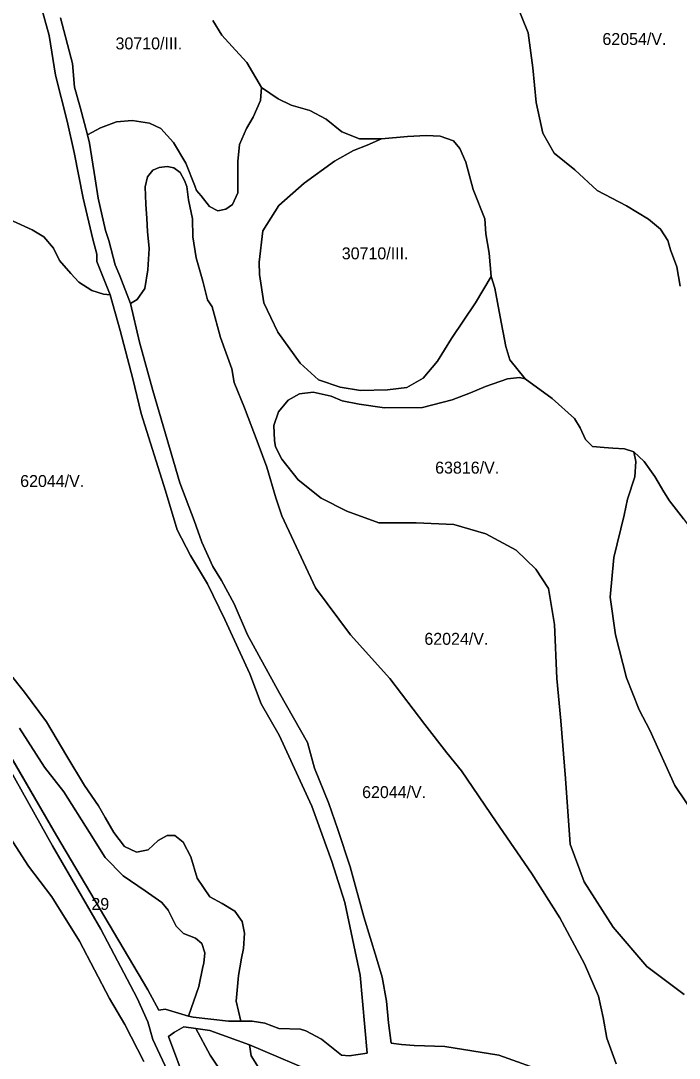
# Model space of a CAD drawing. Extents: x -521621 to -516761, y -1190184 to -1184927.
# Drawn here: x -519249 to -518423, y -1189393 to -1188092 of the extents above; entities that cross this region are included whole.
import ezdxf

# ---------------------------------------------------------------- set-up
doc = ezdxf.new("R2010")
doc.units = 0
doc.layers.add('BPEJ_s', color=7, linetype='Continuous')

msp = doc.modelspace()

# ---------------------------------------------------------------- linework, layer by layer
at = {"layer": 'BPEJ_s'}
for p, q in [((-519204.4, -1189113.9), (-519310.7, -1188931.3)), ((-519250.7, -1188979.3), (-519219.5, -1189028.1)), ((-519219.5, -1189028.1), (-519195.4, -1189059.3)), ((-519195.4, -1189059.3), (-519163.2, -1189110)), ((-519163.2, -1189110), (-519143.6, -1189141.7)), ((-519090, -1189307.3), (-519204.4, -1189113.9)), ((-519143.6, -1189141.7), (-519121, -1189164.3)), ((-519121, -1189164.3), (-519093.4, -1189183.5)), ((-519093.4, -1189183.5), (-519072.3, -1189198)), ((-519072.3, -1189198), (-519064.2, -1189207.6)), ((-519064.2, -1189207.6), (-519054.2, -1189227.7)), ((-519054.2, -1189227.7), (-519045.1, -1189236.8)), ((-519045.1, -1189236.8), (-519030, -1189242.8)), ((-519030, -1189242.8), (-519022, -1189249.3)), ((-519022, -1189249.3), (-519018.5, -1189260.9)), ((-519018.5, -1189260.9), (-519019.5, -1189274)), ((-519021.1, -1189278.8), (-519025.8, -1189303.4)), ((-519019.5, -1189274), (-519021.1, -1189278.8)), ((-519076.3, -1189332.8), (-519090, -1189307.3)), ((-519025.8, -1189303.4), (-519038.7, -1189340.3)), ((-519068.1, -1189331.9), (-519076.3, -1189332.8)), ((-519038.7, -1189340.3), (-519068.1, -1189331.9))]:
    msp.add_line(p, q, dxfattribs=at)
for points in [[(-519310.7, -1188931.3), (-519204.4, -1189113.9), (-519090, -1189307.3), (-519076.3, -1189332.8), (-519068.1, -1189331.9), (-519038.7, -1189340.3), (-519033.1, -1189341.9), (-518988.7, -1189346.7), (-518973.2, -1189346.8), (-518959.1, -1189346.8), (-518943, -1189349.4), (-518925.4, -1189356), (-518898.4, -1189356.8), (-518891.6, -1189358.8), (-518872.1, -1189369.4), (-518846.8, -1189389.4), (-518837.5, -1189390.4), (-518814.6, -1189387), (-518823.5, -1189289), (-518842.7, -1189197.8), (-518859.1, -1189146.7), (-518884.3, -1189077.1), (-518925.3, -1188988), (-518947.6, -1188949), (-518962.1, -1188911.3), (-518993.3, -1188842.9), (-519014.9, -1188798.4), (-519036.3, -1188762.9), (-519053.3, -1188730.6), (-519067.7, -1188681.6), (-519098.2, -1188584.8), (-519108.8, -1188541.2), (-519124.4, -1188480.7), (-519137.3, -1188435.8), (-519153.9, -1188394.1), (-519153.7, -1188385.1), (-519159, -1188366.1), (-519170.9, -1188314.7), (-519182.1, -1188257.4), (-519191.2, -1188218), (-519205.6, -1188160.4), (-519213.8, -1188110.8), (-519224.7, -1188071.4)], [(-519224.7, -1188071.4), (-519213.8, -1188110.8), (-519205.6, -1188160.4), (-519191.2, -1188218), (-519182.1, -1188257.4), (-519170.9, -1188314.7), (-519159, -1188366.1), (-519153.7, -1188385.1), (-519153.9, -1188394.1), (-519137.3, -1188435.8), (-519145.7, -1188435.1), (-519160.1, -1188430.5), (-519176.6, -1188419.9), (-519186.3, -1188409.1), (-519200.9, -1188393), (-519208.2, -1188377.4), (-519220.5, -1188363), (-519234.9, -1188354.2), (-519258.9, -1188343.4)], [(-518422.2, -1188425.1), (-518426.5, -1188400.9), (-518434.5, -1188379.5), (-518437.8, -1188367.6), (-518447, -1188353.4), (-518462, -1188340.9), (-518489.5, -1188324.2), (-518526.2, -1188305), (-518554.5, -1188279.1), (-518580.4, -1188258.3), (-518594.6, -1188233.2), (-518602.9, -1188194.8), (-518607.1, -1188151.4), (-518612.9, -1188107.2), (-518629.6, -1188065.5)], [(-518629.6, -1188065.5), (-518612.9, -1188107.2), (-518607.1, -1188151.4), (-518602.9, -1188194.8), (-518594.6, -1188233.2), (-518580.4, -1188258.3), (-518554.5, -1188279.1), (-518526.2, -1188305), (-518489.5, -1188324.2), (-518462, -1188340.9), (-518447, -1188353.4), (-518437.8, -1188367.6), (-518434.5, -1188379.5), (-518426.5, -1188400.9), (-518422.2, -1188425.1)], [(-519008.5, -1188091.9), (-518997.1, -1188110.1), (-518980, -1188129.2), (-518965.7, -1188144.7), (-518947.5, -1188176), (-518948.7, -1188192.3), (-518957.8, -1188213.3), (-518966.1, -1188227.2), (-518974.8, -1188247.4), (-518977.2, -1188268.8), (-518977.2, -1188308.1), (-518983.6, -1188322.8), (-518991.9, -1188328.3), (-519002.2, -1188330.7), (-519012.5, -1188325.2), (-519023.2, -1188311.7), (-519028.8, -1188304.9), (-519031.1, -1188299.4), (-519042.1, -1188270.6), (-519057.6, -1188244.7), (-519073.4, -1188227.2), (-519087.6, -1188220.5), (-519109.5, -1188217.4), (-519129.3, -1188219.1), (-519149.3, -1188226.4), (-519165.7, -1188235.3), (-519174.9, -1188200.4), (-519181.7, -1188175.6), (-519184.3, -1188145.8), (-519199.5, -1188088.7)], [(-519199.5, -1188088.7), (-519184.3, -1188145.8), (-519181.7, -1188175.6), (-519174.9, -1188200.4), (-519165.7, -1188235.3), (-519163, -1188245.8), (-519155.8, -1188290.4), (-519152, -1188314.5), (-519142.9, -1188355.4), (-519138.9, -1188367.7), (-519130.8, -1188398.4), (-519124.9, -1188412), (-519111.8, -1188446.6), (-519100.2, -1188495.2), (-519083.8, -1188556), (-519049.7, -1188671.8), (-519031.7, -1188719.1), (-519022.3, -1188746.2), (-519008.4, -1188776.5), (-518997.4, -1188794.1), (-518981.8, -1188823.6), (-518964.8, -1188862.2), (-518924.6, -1188935.3), (-518889.5, -1188997.5), (-518880.9, -1189029.4), (-518863, -1189074), (-518851.7, -1189106.3), (-518836.2, -1189153.4), (-518818.8, -1189215.9), (-518803.2, -1189267.6), (-518795.9, -1189291.4), (-518790.7, -1189321.8), (-518788, -1189348.8), (-518784.8, -1189374.2), (-518771.9, -1189376), (-518756, -1189377.2), (-518717.4, -1189378.6), (-518649.6, -1189389.2), (-518586.3, -1189412)], [(-518417.8, -1188716.8), (-518435.5, -1188694.4), (-518442.8, -1188683), (-518453.9, -1188663.6), (-518467.4, -1188644.9), (-518480.4, -1188633), (-518491.9, -1188629.1), (-518506.6, -1188628.3), (-518517.7, -1188627.5), (-518532, -1188625.9), (-518541.1, -1188617.2), (-518547.8, -1188602.9), (-518554.6, -1188591.1), (-518582.8, -1188566), (-518616.7, -1188541.3), (-518635.7, -1188517.6), (-518641, -1188500.9), (-518647.8, -1188463.6), (-518654.5, -1188427.5), (-518659.2, -1188412.8), (-518661.6, -1188383.5), (-518666, -1188359.3), (-518667.2, -1188340.6), (-518681.9, -1188303.7), (-518691, -1188269.6), (-518698.5, -1188252.6), (-518706.4, -1188242.6), (-518723.1, -1188237.1), (-518740.9, -1188235.9), (-518764.3, -1188237.5), (-518796.8, -1188240.3), (-518824.2, -1188240.3), (-518846.4, -1188231.5), (-518866.2, -1188215.7), (-518886.8, -1188204.6), (-518910.2, -1188198.2), (-518926.5, -1188190.3), (-518947.5, -1188176), (-518965.7, -1188144.7), (-518980, -1188129.2), (-518997.1, -1188110.1), (-519008.5, -1188091.9)], [(-519165.7, -1188235.3), (-519149.3, -1188226.4), (-519129.3, -1188219.1), (-519109.5, -1188217.4), (-519087.6, -1188220.5), (-519073.4, -1188227.2), (-519057.6, -1188244.7), (-519042.1, -1188270.6), (-519031.1, -1188299.4), (-519028.8, -1188304.9), (-519023.2, -1188311.7), (-519012.5, -1188325.2), (-519002.2, -1188330.7), (-518991.9, -1188328.3), (-518983.6, -1188322.8), (-518977.2, -1188308.1), (-518977.2, -1188287.9), (-518977.2, -1188268.8), (-518974.8, -1188247.4), (-518966.1, -1188227.2), (-518957.8, -1188213.3), (-518948.7, -1188192.3), (-518947.5, -1188176)], [(-518947.5, -1188176), (-518926.5, -1188190.3), (-518910.2, -1188198.2), (-518886.8, -1188204.6), (-518866.2, -1188215.7), (-518846.4, -1188231.5), (-518824.2, -1188240.3), (-518796.8, -1188240.3)], [(-519111.8, -1188446.6), (-519124.9, -1188412), (-519130.8, -1188398.4), (-519138.9, -1188367.7), (-519142.9, -1188355.4), (-519152, -1188314.5), (-519155.8, -1188290.4), (-519163, -1188245.8), (-519165.7, -1188235.3)], [(-518796.8, -1188240.3), (-518814.7, -1188248.2), (-518832.1, -1188254.9), (-518855.9, -1188268.4), (-518893.6, -1188295.8), (-518925.7, -1188324), (-518945.5, -1188355.7), (-518950.3, -1188395), (-518949.9, -1188410.5), (-518944.3, -1188445.8), (-518926.9, -1188482.7), (-518898.7, -1188521.5), (-518875.7, -1188542.6), (-518848.8, -1188551.7), (-518823, -1188555.7), (-518789.3, -1188554.9), (-518765.1, -1188552.1), (-518744.5, -1188540.6), (-518726.7, -1188519.2), (-518709.2, -1188490.6), (-518679.1, -1188445.8), (-518659.2, -1188412.8)], [(-518586.3, -1189412), (-518649.6, -1189389.2), (-518717.4, -1189378.6), (-518756, -1189377.2), (-518771.9, -1189376), (-518784.8, -1189374.2), (-518788, -1189348.8), (-518790.7, -1189321.8), (-518795.9, -1189291.4), (-518803.2, -1189267.6), (-518818.8, -1189215.9), (-518836.2, -1189153.4), (-518851.7, -1189106.3), (-518863, -1189074), (-518880.9, -1189029.4), (-518889.5, -1188997.5), (-518924.6, -1188935.3), (-518964.8, -1188862.2), (-518981.8, -1188823.6), (-518997.4, -1188794.1), (-519008.4, -1188776.5), (-519022.3, -1188746.2), (-519031.7, -1188719.1), (-519049.7, -1188671.8), (-519083.8, -1188556), (-519100.2, -1188495.2), (-519111.8, -1188446.6), (-519103.4, -1188441.6), (-519093.8, -1188427.8), (-519089.9, -1188404.7), (-519088.4, -1188378), (-519090.5, -1188356.3), (-519091.1, -1188340.2), (-519092.2, -1188322.3), (-519093.4, -1188300.4), (-519090.5, -1188287.9), (-519083.6, -1188279.6), (-519075.5, -1188276.2), (-519065.5, -1188275), (-519057.2, -1188276.8), (-519049.2, -1188282.3), (-519044, -1188292.5), (-519041.1, -1188300), (-519039, -1188316.7), (-519033.8, -1188340.4), (-519033.4, -1188363.2), (-519029.4, -1188389.4), (-519020.7, -1188418.6), (-519015.1, -1188442), (-519009.4, -1188451), (-518998.8, -1188489.3), (-518984.6, -1188528.7), (-518981.5, -1188546), (-518968.6, -1188577.5), (-518951.5, -1188622.6), (-518940.5, -1188652.2), (-518929.4, -1188690.5), (-518921.7, -1188713.1), (-518879.6, -1188803.3), (-518835.5, -1188862.1), (-518786.5, -1188917.1), (-518742.4, -1188974.9), (-518714.9, -1189010.2), (-518696.5, -1189032.7), (-518653, -1189096.9), (-518608.5, -1189161.1), (-518573.3, -1189217), (-518542.3, -1189275), (-518524.7, -1189315.4), (-518518.7, -1189342), (-518514, -1189368), (-518502.4, -1189400.1)], [(-518502.4, -1189400.1), (-518514, -1189368), (-518518.7, -1189342), (-518524.7, -1189315.4), (-518542.3, -1189275), (-518573.3, -1189217), (-518608.5, -1189161.1), (-518653, -1189096.9), (-518696.5, -1189032.7), (-518714.9, -1189010.2), (-518742.4, -1188974.9), (-518786.5, -1188917.1), (-518835.5, -1188862.1), (-518879.6, -1188803.3), (-518921.7, -1188713.1), (-518929.4, -1188690.5), (-518940.5, -1188652.2), (-518951.5, -1188622.6), (-518968.6, -1188577.5), (-518981.5, -1188546), (-518984.6, -1188528.7), (-518998.8, -1188489.3), (-519009.4, -1188451), (-519015.1, -1188442), (-519020.7, -1188418.6), (-519029.4, -1188389.4), (-519033.4, -1188363.2), (-519033.8, -1188340.4), (-519039, -1188316.7), (-519041.1, -1188300), (-519044, -1188292.5), (-519049.2, -1188282.3), (-519057.2, -1188276.8), (-519065.5, -1188275), (-519075.5, -1188276.2), (-519083.6, -1188279.6), (-519090.5, -1188287.9), (-519093.4, -1188300.4), (-519092.2, -1188322.3), (-519091.1, -1188340.2), (-519090.5, -1188356.3), (-519088.4, -1188378), (-519089.9, -1188404.7), (-519093.8, -1188427.8), (-519103.4, -1188441.6), (-519111.8, -1188446.6)], [(-519258.9, -1188343.4), (-519234.9, -1188354.2), (-519220.5, -1188363), (-519208.2, -1188377.4), (-519200.9, -1188393), (-519186.3, -1188409.1), (-519176.6, -1188419.9), (-519160.1, -1188430.5), (-519145.7, -1188435.1), (-519137.3, -1188435.8), (-519124.4, -1188480.7), (-519108.8, -1188541.2), (-519098.2, -1188584.8), (-519067.7, -1188681.6), (-519053.3, -1188730.6), (-519036.3, -1188762.9), (-519014.9, -1188798.4), (-518993.3, -1188842.9), (-518962.1, -1188911.3), (-518947.6, -1188949), (-518925.3, -1188988), (-518884.3, -1189077.1), (-518859.1, -1189146.7), (-518842.7, -1189197.8), (-518823.5, -1189289), (-518814.6, -1189387), (-518837.5, -1189390.4), (-518846.8, -1189389.4), (-518872.1, -1189369.4), (-518891.6, -1189358.8), (-518898.4, -1189356.8), (-518925.4, -1189356), (-518943, -1189349.4), (-518959.1, -1189346.8), (-518973.2, -1189346.8), (-518978.9, -1189321.8), (-518976, -1189289.6), (-518974.6, -1189279.9), (-518972.3, -1189267.8), (-518969.7, -1189255.5), (-518968.8, -1189236.3), (-518971.7, -1189221.7), (-518980.9, -1189209), (-518996.7, -1189199.3), (-519012, -1189191), (-519028, -1189167.4), (-519036.1, -1189140.7), (-519045.6, -1189122.1), (-519056.2, -1189114.1), (-519065.7, -1189114.1), (-519076.8, -1189120.1), (-519089.3, -1189131.7), (-519103.9, -1189134.7), (-519119, -1189127.6), (-519132.6, -1189110), (-519143.6, -1189091.4), (-519151.7, -1189076.9), (-519169.2, -1189051.2), (-519191.4, -1189014.5), (-519217, -1188971.3), (-519244.6, -1188934), (-519284.3, -1188884.8)], [(-518659.2, -1188412.8), (-518654.5, -1188427.5), (-518647.8, -1188463.6), (-518641, -1188500.9), (-518635.7, -1188517.6), (-518616.7, -1188541.3)], [(-518417, -1189313.3), (-518464, -1189278), (-518506.2, -1189228.9), (-518542.4, -1189172), (-518560.1, -1189125), (-518566, -1189042.6), (-518571.8, -1188970), (-518576.7, -1188917.1), (-518579.7, -1188849.4), (-518587.5, -1188804.3), (-518603.2, -1188779.8), (-518627.7, -1188756.2), (-518665.9, -1188735.6), (-518706.1, -1188723.9), (-518753.2, -1188721.9), (-518800.2, -1188721.9), (-518840.4, -1188707.2), (-518872.5, -1188690.8), (-518901.5, -1188668), (-518921.9, -1188641.8), (-518929.6, -1188626.5), (-518931.1, -1188618.4), (-518931.9, -1188599.6), (-518925.9, -1188582.7), (-518914, -1188568.1), (-518899.8, -1188560.2), (-518882.5, -1188557.9), (-518859.8, -1188562.9), (-518846.3, -1188568.8), (-518824.8, -1188573.2), (-518792.9, -1188577.7), (-518745.2, -1188577.1), (-518708.3, -1188567.7), (-518685.2, -1188558.8), (-518666.2, -1188551), (-518638.9, -1188541.2), (-518623.7, -1188539.6), (-518616.7, -1188541.3), (-518582.8, -1188566), (-518554.6, -1188591.1), (-518547.8, -1188602.9), (-518541.1, -1188617.2), (-518532, -1188625.9), (-518517.7, -1188627.5), (-518506.6, -1188628.3), (-518491.9, -1188629.1), (-518480.4, -1188633), (-518477.7, -1188644.9), (-518479.2, -1188664), (-518488.4, -1188692.1), (-518492.5, -1188712.1), (-518505.2, -1188765.1), (-518510.1, -1188815.1), (-518503.2, -1188862.1), (-518489.5, -1188916.1), (-518473.8, -1188956.3), (-518460.1, -1188981.8), (-518428.8, -1189051.4), (-518400.3, -1189093.6)], [(-518616.7, -1188541.3), (-518623.7, -1188539.6), (-518638.9, -1188541.2), (-518666.2, -1188551), (-518685.2, -1188558.8), (-518708.3, -1188567.7), (-518745.2, -1188577.1), (-518792.9, -1188577.7), (-518824.8, -1188573.2), (-518846.3, -1188568.8), (-518859.8, -1188562.9), (-518882.5, -1188557.9), (-518899.8, -1188560.2), (-518914, -1188568.1), (-518925.9, -1188582.7), (-518931.9, -1188599.6), (-518931.1, -1188618.4), (-518929.6, -1188626.5), (-518921.9, -1188641.8), (-518901.5, -1188668), (-518872.5, -1188690.8), (-518840.4, -1188707.2), (-518800.2, -1188721.9), (-518753.2, -1188721.9), (-518706.1, -1188723.9), (-518665.9, -1188735.6), (-518627.7, -1188756.2), (-518603.2, -1188779.8), (-518587.5, -1188804.3), (-518579.7, -1188849.4), (-518576.7, -1188917.1), (-518571.8, -1188970), (-518566, -1189042.6), (-518560.1, -1189125), (-518542.4, -1189172), (-518506.2, -1189228.9), (-518464, -1189278), (-518417, -1189313.3)], [(-518400.3, -1189093.6), (-518428.8, -1189051.4), (-518460.1, -1188981.8), (-518473.8, -1188956.3), (-518489.5, -1188916.1), (-518503.2, -1188862.1), (-518510.1, -1188815.1), (-518505.2, -1188765.1), (-518492.5, -1188712.1), (-518488.4, -1188692.1), (-518479.2, -1188664), (-518477.7, -1188644.9), (-518480.4, -1188633)], [(-518480.4, -1188633), (-518467.4, -1188644.9), (-518453.9, -1188663.6), (-518442.8, -1188683), (-518435.5, -1188694.4), (-518417.8, -1188716.8), (-518378.9, -1188770)], [(-519284.3, -1188884.8), (-519244.6, -1188934), (-519217, -1188971.3), (-519191.4, -1189014.5), (-519169.2, -1189051.2), (-519151.7, -1189076.9), (-519143.6, -1189091.4), (-519132.6, -1189110), (-519119, -1189127.6), (-519103.9, -1189134.7), (-519089.3, -1189131.7), (-519076.8, -1189120.1), (-519065.7, -1189114.1), (-519056.2, -1189114.1), (-519045.6, -1189122.1), (-519036.1, -1189140.7), (-519028, -1189167.4), (-519012, -1189191), (-518996.7, -1189199.3), (-518980.9, -1189209), (-518971.7, -1189221.7), (-518968.8, -1189236.3), (-518969.7, -1189255.5), (-518972.3, -1189267.8), (-518974.6, -1189279.9), (-518976, -1189289.6), (-518978.9, -1189321.8), (-518973.2, -1189346.8), (-518988.7, -1189346.7), (-519033.1, -1189341.9), (-519038.7, -1189340.3), (-519025.8, -1189303.4), (-519021.1, -1189278.8), (-519019.5, -1189274), (-519018.5, -1189260.9), (-519022, -1189249.3), (-519030, -1189242.8), (-519045.1, -1189236.8), (-519054.2, -1189227.7), (-519064.2, -1189207.6), (-519072.3, -1189198), (-519093.4, -1189183.5), (-519121, -1189164.3), (-519143.6, -1189141.7), (-519163.2, -1189110), (-519195.4, -1189059.3), (-519219.5, -1189028.1), (-519250.7, -1188979.3)], [(-519271.1, -1189017), (-519209.5, -1189126.9), (-519148.7, -1189231.4), (-519103.1, -1189317.9), (-519089.7, -1189347.7), (-519083.6, -1189369.9), (-519062.9, -1189414.3)], [(-519062.9, -1189414.3), (-519083.6, -1189369.9), (-519089.7, -1189347.7), (-519103.1, -1189317.9), (-519148.7, -1189231.4), (-519209.5, -1189126.9), (-519271.1, -1189017)], [(-519094.8, -1189397.3), (-519118.6, -1189351), (-519137.8, -1189318.3), (-519175.8, -1189246.3), (-519210.5, -1189191), (-519239.6, -1189152.3), (-519300.9, -1189057.7)], [(-519300.9, -1189057.7), (-519239.6, -1189152.3), (-519210.5, -1189191), (-519175.8, -1189246.3), (-519137.8, -1189318.3), (-519118.6, -1189351), (-519094.8, -1189397.3)], [(-518997.4, -1189544), (-519063.9, -1189366), (-519056.5, -1189360.7), (-519044.8, -1189353.8), (-519029.5, -1189355.9), (-519011.7, -1189389.6), (-518977.5, -1189440.5)], [(-518870.1, -1189415.6), (-518962.4, -1189376.5), (-519012, -1189358.3), (-519029.5, -1189355.9), (-519044.8, -1189353.8), (-519056.5, -1189360.7), (-519063.9, -1189366), (-518997.4, -1189544)], [(-518977.5, -1189440.5), (-519011.7, -1189389.6), (-519029.5, -1189355.9), (-519012, -1189358.3), (-518962.4, -1189376.5), (-518960.1, -1189390.3), (-518951.1, -1189404.8)], [(-518951.1, -1189404.8), (-518960.1, -1189390.3), (-518962.4, -1189376.5), (-518870.1, -1189415.6)]]:
    msp.add_lwpolyline(points, dxfattribs=at)
msp.add_lwpolyline([(-518796.8, -1188240.3), (-518764.3, -1188237.5), (-518740.9, -1188235.9), (-518723.1, -1188237.1), (-518706.4, -1188242.6), (-518698.5, -1188252.6), (-518691, -1188269.6), (-518681.9, -1188303.7), (-518667.2, -1188340.6), (-518666, -1188359.3), (-518661.6, -1188383.5), (-518659.2, -1188412.8), (-518679.1, -1188445.8), (-518709.2, -1188490.6), (-518726.7, -1188519.2), (-518744.5, -1188540.6), (-518765.1, -1188552.1), (-518789.3, -1188554.9), (-518823, -1188555.7), (-518848.8, -1188551.7), (-518875.7, -1188542.6), (-518898.7, -1188521.5), (-518926.9, -1188482.7), (-518944.3, -1188445.8), (-518949.9, -1188410.5), (-518950.3, -1188395), (-518945.5, -1188355.7), (-518925.7, -1188324), (-518893.6, -1188295.8), (-518855.9, -1188268.4), (-518832.1, -1188254.9), (-518814.7, -1188248.2)], close=True, dxfattribs=at)

# ---------------------------------------------------------------- texts
for s, p in [('62054/V.', (-518519.7, -1188122.6)), ('30710/III.', (-519130.4, -1188128.1)), ('30710/III.', (-518846.6, -1188391.4)), ('63816/V.', (-518729.5, -1188660.1)), ('62044/V.', (-519250, -1188676.9)), ('62024/V.', (-518743, -1188874.8)), ('62044/V.', (-518821.1, -1189067)), ('29', (-519160.7, -1189207.3))]:
    msp.add_text(s, height=15, dxfattribs=at).set_placement(p)

doc.saveas('drawing.dxf')
